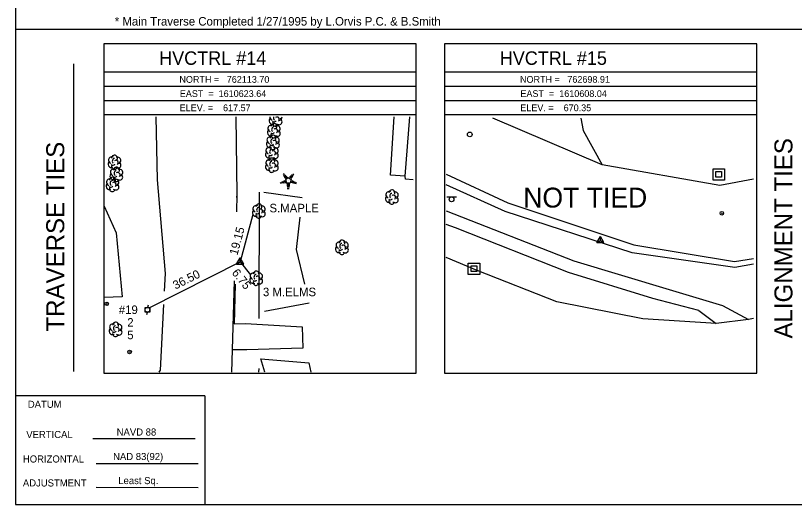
# Model space of a CAD drawing. Extents: x 1609637 to 1610277, y 761117 to 761537.
# Drawn here: x 1609637.2 to 1609911.6, y 761117.3 to 761289.4 of the extents above; entities that cross this region are included whole.
import ezdxf

# ---------------------------------------------------------------- set-up
doc = ezdxf.new("R2010")
doc.units = 0
for name, color, linetype in [('CPSM', 7, 'Continuous'), ('Default', 7, 'Continuous'), ('DS', 7, 'Continuous'), ('L_C', 7, 'Continuous'), ('LABL', 7, 'Continuous'), ('LAWA', 7, 'Continuous'), ('LBC', 7, 'Continuous'), ('LBF', 7, 'Continuous'), ('LFNC', 7, 'Continuous'), ('LSH', 7, 'Continuous'), ('LTC', 7, 'Continuous'), ('LTD', 7, 'Continuous'), ('NBL2', 7, 'Continuous'), ('PET', 7, 'Continuous'), ('PEU', 7, 'Continuous'), ('RDF', 7, 'Continuous'), ('RGR', 7, 'Continuous'), ('RSW', 7, 'Continuous'), ('SSGN', 7, 'Continuous'), ('U_C', 7, 'Continuous'), ('UP', 7, 'Continuous'), ('UPGW', 7, 'Continuous'), ('USMH', 7, 'Continuous'), ('UWV', 7, 'Continuous')]:
    doc.layers.add(name, color=color, linetype=linetype)

msp = doc.modelspace()

# ---------------------------------------------------------------- linework, layer by layer
at = {"layer": 'CPSM'}
for p, q in [((1609842.03, 761209.5), (1609843.28, 761211.67)), ((1609844.53, 761209.5), (1609843.28, 761211.67)), ((1609843.28, 761210.22), (1609843.28, 761211.67)), ((1609842.03, 761209.5), (1609843.28, 761210.22)), ((1609842.03, 761209.5), (1609844.53, 761209.5)), ((1609843.28, 761210.22), (1609843.28, 761210.22)), ((1609843.28, 761210.22), (1609844.53, 761209.5)), ((1609715.11, 761201.94), (1609716.36, 761204.11)), ((1609715.11, 761201.94), (1609716.36, 761202.66)), ((1609717.61, 761201.94), (1609716.36, 761204.11)), ((1609716.36, 761202.66), (1609716.36, 761204.11)), ((1609716.36, 761202.66), (1609716.36, 761202.66)), ((1609716.36, 761202.66), (1609717.61, 761201.94)), ((1609715.11, 761201.94), (1609717.61, 761201.94))]:
    msp.add_line(p, q, dxfattribs=at)
at = {"layer": 'Default'}
for p, q in [((1609720.83, 761219.38), (1609716.36, 761202.66)), ((1609684.52, 761186.67), (1609716.36, 761202.66)), ((1609716.36, 761202.66), (1609719.99, 761198.15))]:
    msp.add_line(p, q, dxfattribs=at)
at = {"layer": 'DS'}
for p, q in [((1609882.99, 761235.49), (1609886.99, 761235.49)), ((1609882.99, 761231.49), (1609882.99, 761235.49)), ((1609886.99, 761235.49), (1609886.99, 761231.49)), ((1609883.99, 761232.49), (1609883.99, 761234.49)), ((1609883.99, 761234.49), (1609885.99, 761234.49)), ((1609885.99, 761232.49), (1609883.99, 761232.49)), ((1609884.99, 761233.49), (1609884.99, 761233.49)), ((1609884.99, 761233.49), (1609884.99, 761233.49)), ((1609885.99, 761234.49), (1609885.99, 761232.49)), ((1609886.99, 761231.49), (1609882.99, 761231.49)), ((1609796.74, 761202.29), (1609800.74, 761202.29)), ((1609796.74, 761198.29), (1609796.74, 761202.29)), ((1609800.74, 761202.29), (1609800.74, 761198.29)), ((1609797.74, 761199.29), (1609797.74, 761201.29)), ((1609797.74, 761201.29), (1609799.74, 761201.29)), ((1609798.74, 761200.29), (1609798.74, 761200.29)), ((1609798.74, 761200.29), (1609798.74, 761200.29)), ((1609799.74, 761201.29), (1609799.74, 761199.29)), ((1609800.74, 761198.29), (1609796.74, 761198.29)), ((1609799.74, 761199.29), (1609797.74, 761199.29))]:
    msp.add_line(p, q, dxfattribs=at)
at = {"layer": 'LABL'}
msp.add_lwpolyline([(1609668.5, 761222.29), (1609672.69, 761212.96), (1609674.75, 761190.41), (1609668.5, 761190.13)], dxfattribs=at)
at = {"layer": 'LAWA'}
for points in [[(1609724.66, 761227.21), (1609738.2, 761225.35)], [(1609737.43, 761218.44), (1609736.14, 761207.04), (1609739.05, 761194.79)], [(1609740.64, 761188.11), (1609724.98, 761185.21)], [(1609725, 761163.83), (1609723.63, 761168.5), (1609740.5, 761167.1), (1609741.22, 761163.83)]]:
    msp.add_lwpolyline(points, dxfattribs=at)
at = {"layer": 'LBC'}
msp.add_lwpolyline([(1609777.33, 761231.64), (1609774.55, 761231.86), (1609774.53, 761232.88), (1609776.18, 761253.73)], dxfattribs=at)
at = {"layer": 'LBF'}
msp.add_lwpolyline([(1609774.53, 761232.88), (1609769.27, 761233.25), (1609770.64, 761253.73)], dxfattribs=at)
at = {"layer": 'LFNC'}
for points in [[(1609723.05, 761182.72), (1609723.2, 761227.22)], [(1609722.96, 761163.83), (1609723.03, 761165.19)]]:
    msp.add_lwpolyline(points, dxfattribs=at)
at = {"layer": 'LSH'}
for p, q in [((1609728.83, 761253.05), (1609728.83, 761253.05)), ((1609728.83, 761253.05), (1609728.83, 761253.05)), ((1609728.21, 761248.95), (1609728.21, 761248.95)), ((1609728.21, 761248.95), (1609728.21, 761248.95)), ((1609727.88, 761244.83), (1609727.88, 761244.83)), ((1609727.88, 761244.83), (1609727.88, 761244.83)), ((1609727.5, 761241.14), (1609727.5, 761241.14)), ((1609727.5, 761241.14), (1609727.5, 761241.14)), ((1609727.49, 761236.79), (1609727.49, 761236.79)), ((1609727.49, 761236.79), (1609727.49, 761236.79))]:
    msp.add_line(p, q, dxfattribs=at)
for centre in [(1609728.26, 761250.38), (1609727.93, 761246.27), (1609727.55, 761242.58), (1609727.53, 761238.22)]:
    msp.add_arc(centre, 1.05, 335.5272, 180.9563, dxfattribs=at)
for centre, major_axis, ratio, start_param, end_param in [((1609727.74, 761252.34), (0.58, -1.04), 0.959034, 3.141593, 6.283185), ((1609728.04, 761253.72), (1.21, -0.51), 0.895232, 3.576686, 4.712389), ((1609728.83, 761251.55), (0.26, 1.06), 0.942809, 1.570796, 4.712389), ((1609728.37, 761252.3), (-0.625, -0.083), 0.423636, 0, 3.141593), ((1609728.62, 761253.51), (-0.208, -0.792), 0.645439, 4.608624, 6.283185), ((1609729.33, 761252.89), (-0.5, 0.667), 0.989748, 3.141593, 6.283185), ((1609729.83, 761252.22), (-1.09, 0.79), 0.841452, 1.570796, 4.712389), ((1609729.87, 761253.64), (-1.14, -0.48), 0.949671, 1.570796, 2.79864), ((1609727.13, 761248.24), (0.58, -1.04), 0.959034, 3.141593, 6.283185), ((1609727.42, 761249.62), (1.21, -0.51), 0.895232, 1.570796, 4.712389), ((1609728, 761249.41), (-0.208, -0.792), 0.645439, 3.141593, 6.283185), ((1609728.71, 761248.78), (-0.5, 0.667), 0.989748, 3.141593, 6.283185), ((1609729.21, 761248.12), (-1.09, 0.79), 0.841452, 1.570796, 4.712389), ((1609729.25, 761249.53), (-1.14, -0.48), 0.949671, 1.570796, 4.712389), ((1609727.09, 761245.5), (1.21, -0.51), 0.895232, 1.570796, 4.712389), ((1609727.68, 761245.29), (-0.208, -0.792), 0.645439, 3.141593, 6.283185), ((1609728.21, 761247.45), (0.26, 1.06), 0.942809, 1.570796, 4.712389), ((1609727.75, 761248.2), (-0.625, -0.083), 0.423636, 0, 3.141593), ((1609728.93, 761245.42), (-1.14, -0.48), 0.949671, 1.570796, 4.712389), ((1609726.8, 761244.12), (0.58, -1.04), 0.959034, 3.141593, 6.283185), ((1609727.88, 761243.33), (0.26, 1.06), 0.942809, 1.570796, 4.712389), ((1609727.43, 761244.08), (-0.625, -0.083), 0.423636, 0, 3.141593), ((1609728.38, 761244.67), (-0.5, 0.667), 0.989748, 3.141593, 6.283185), ((1609728.88, 761244), (-1.09, 0.79), 0.841452, 1.570796, 4.712389), ((1609726.42, 761240.43), (0.58, -1.04), 0.959034, 3.141593, 6.283185), ((1609726.71, 761241.81), (1.21, -0.51), 0.895232, 1.570796, 4.712389), ((1609727.29, 761241.6), (-0.208, -0.792), 0.645439, 3.141593, 6.283185), ((1609728, 761240.98), (-0.5, 0.667), 0.989748, 3.141593, 6.283185), ((1609728.5, 761240.31), (-1.09, 0.79), 0.841452, 1.570796, 4.712389), ((1609728.54, 761241.73), (-1.14, -0.48), 0.949671, 1.570796, 4.712389), ((1609726.7, 761237.46), (1.21, -0.51), 0.895232, 1.570796, 4.712389), ((1609727.5, 761239.64), (0.26, 1.06), 0.942809, 1.570796, 4.712389), ((1609727.04, 761240.39), (-0.625, -0.083), 0.423636, 0, 3.141593), ((1609727.28, 761237.25), (-0.208, -0.792), 0.645439, 3.141593, 6.283185), ((1609728.53, 761237.37), (-1.14, -0.48), 0.949671, 1.570796, 4.712389), ((1609726.4, 761236.08), (0.58, -1.04), 0.959034, 3.141593, 6.283185), ((1609727.49, 761235.29), (0.26, 1.06), 0.942809, 1.570796, 4.712389), ((1609727.03, 761236.04), (-0.625, -0.083), 0.423636, 0, 3.141593), ((1609727.99, 761236.62), (-0.5, 0.667), 0.989748, 3.141593, 6.283185), ((1609728.49, 761235.96), (-1.09, 0.79), 0.841452, 1.570796, 4.712389)]:
    msp.add_ellipse(centre, major_axis=major_axis, ratio=ratio, start_param=start_param, end_param=end_param, dxfattribs=at)
at = {"layer": 'LTC'}
for p, q in [((1609731.46, 761233.51), (1609731.81, 761233.77)), ((1609731.67, 761233.05), (1609732.2, 761233.43)), ((1609731.88, 761232.58), (1609732.58, 761233.09)), ((1609732.09, 761232.12), (1609732.96, 761232.75)), ((1609732.31, 761231.66), (1609733.32, 761232.4)), ((1609733.32, 761232.4), (1609734.32, 761231.67)), ((1609733.74, 761232.71), (1609734.55, 761232.12)), ((1609734.11, 761233.06), (1609734.79, 761232.56)), ((1609734.48, 761233.41), (1609735.03, 761233.01)), ((1609734.86, 761233.75), (1609735.27, 761233.45)), ((1609730.49, 761230.79), (1609730.64, 761230.33)), ((1609730.95, 761231.01), (1609731.16, 761230.36)), ((1609731.4, 761231.23), (1609731.67, 761230.39)), ((1609731.86, 761231.44), (1609732.19, 761230.42)), ((1609732.31, 761231.66), (1609732.7, 761230.47)), ((1609733.93, 761230.47), (1609732.7, 761230.47)), ((1609733.89, 761229.97), (1609732.75, 761229.97)), ((1609734.32, 761231.67), (1609733.93, 761230.47)), ((1609734.76, 761231.4), (1609734.42, 761230.36)), ((1609735.2, 761231.15), (1609734.91, 761230.27)), ((1609735.65, 761230.9), (1609735.41, 761230.17)), ((1609736.09, 761230.65), (1609735.9, 761230.08)), ((1609733.81, 761229.47), (1609732.82, 761229.47)), ((1609733.72, 761228.97), (1609732.89, 761228.97)), ((1609733.64, 761228.47), (1609732.96, 761228.47))]:
    msp.add_line(p, q, dxfattribs=at)
at = {"layer": 'LTD'}
for p, q in [((1609672.05, 761237.81), (1609672.05, 761237.81)), ((1609672.05, 761237.81), (1609672.05, 761237.81)), ((1609672.72, 761233.55), (1609672.72, 761233.55)), ((1609672.72, 761233.55), (1609672.72, 761233.55)), ((1609671.33, 761230.05), (1609671.33, 761230.05)), ((1609671.33, 761230.05), (1609671.33, 761230.05)), ((1609769.79, 761225.58), (1609769.79, 761225.58)), ((1609769.79, 761225.58), (1609769.79, 761225.58)), ((1609722.92, 761220.65), (1609722.92, 761220.65)), ((1609722.92, 761220.65), (1609722.92, 761220.65)), ((1609752.2, 761207.89), (1609752.2, 761207.89)), ((1609752.2, 761207.89), (1609752.2, 761207.89)), ((1609721.99, 761196.98), (1609721.99, 761196.98)), ((1609721.99, 761196.98), (1609721.99, 761196.98)), ((1609672.45, 761178.96), (1609672.45, 761178.96)), ((1609672.45, 761178.96), (1609672.45, 761178.96))]:
    msp.add_line(p, q, dxfattribs=at)
for centre in [(1609672.09, 761239.24), (1609672.76, 761234.98), (1609671.38, 761231.49), (1609769.84, 761227.01), (1609722.96, 761222.09), (1609752.24, 761209.33), (1609722.04, 761198.41), (1609672.5, 761180.39)]:
    msp.add_arc(centre, 1.05, 335.5272, 180.9563, dxfattribs=at)
for centre, major_axis, ratio, start_param, end_param in [((1609670.96, 761237.1), (0.58, -1.04), 0.959034, 3.141593, 6.283185), ((1609671.26, 761238.48), (1.21, -0.51), 0.895232, 1.570796, 4.712389), ((1609671.84, 761238.27), (-0.208, -0.792), 0.645439, 3.141593, 6.283185), ((1609672.55, 761237.64), (-0.5, 0.667), 0.989748, 3.141593, 6.283185), ((1609673.05, 761236.98), (-1.09, 0.79), 0.841452, 1.570796, 4.712389), ((1609673.09, 761238.39), (-1.14, -0.48), 0.949671, 1.570796, 4.712389), ((1609671.93, 761234.22), (1.21, -0.51), 0.895232, 1.570796, 4.712389), ((1609672.05, 761236.31), (0.26, 1.06), 0.942809, 1.570796, 4.712389), ((1609671.59, 761237.06), (-0.625, -0.083), 0.423636, 0, 3.141593), ((1609673.76, 761234.13), (-1.14, -0.48), 0.949671, 1.570796, 4.712389), ((1609671.63, 761232.84), (0.58, -1.04), 0.959034, 3.141593, 6.283185), ((1609672.26, 761232.8), (-0.625, -0.083), 0.423636, 0, 3.141593), ((1609672.51, 761234.01), (-0.208, -0.792), 0.645439, 3.141593, 6.283185), ((1609673.22, 761233.38), (-0.5, 0.667), 0.989748, 3.141593, 6.283185), ((1609673.72, 761232.72), (-1.09, 0.79), 0.841452, 1.570796, 4.712389), ((1609670.25, 761229.35), (0.58, -1.04), 0.959034, 3.141593, 6.283185), ((1609670.54, 761230.72), (1.21, -0.51), 0.895232, 1.570796, 4.712389), ((1609671.12, 761230.51), (-0.208, -0.792), 0.645439, 3.141593, 6.283185), ((1609671.83, 761229.89), (-0.5, 0.667), 0.989748, 3.141593, 6.283185), ((1609672.72, 761232.05), (0.26, 1.06), 0.942809, 1.570796, 4.712389), ((1609672.33, 761229.22), (-1.09, 0.79), 0.841452, 1.570796, 4.712389), ((1609672.37, 761230.64), (-1.14, -0.48), 0.949671, 1.570796, 4.712389), ((1609671.33, 761228.55), (0.26, 1.06), 0.942809, 1.570796, 4.712389), ((1609670.87, 761229.3), (-0.625, -0.083), 0.423636, 0, 3.141593), ((1609769, 761226.25), (1.21, -0.51), 0.895232, 1.570796, 4.712389), ((1609769.58, 761226.04), (-0.208, -0.792), 0.645439, 3.141593, 6.283185), ((1609770.83, 761226.16), (-1.14, -0.48), 0.949671, 1.570796, 4.712389), ((1609768.71, 761224.87), (0.58, -1.04), 0.959034, 3.141593, 6.283185), ((1609769.79, 761224.08), (0.26, 1.06), 0.942809, 1.570796, 4.712389), ((1609769.33, 761224.83), (-0.625, -0.083), 0.423636, 0, 3.141593), ((1609770.29, 761225.41), (-0.5, 0.667), 0.989748, 3.141593, 6.283185), ((1609770.79, 761224.75), (-1.09, 0.79), 0.841452, 1.570796, 4.712389), ((1609722.12, 761221.32), (1.21, -0.51), 0.895232, 1.570796, 4.712389), ((1609722.71, 761221.11), (-0.208, -0.792), 0.645439, 3.141593, 6.283185), ((1609723.42, 761220.49), (-0.5, 0.667), 0.989748, 3.141593, 6.283185), ((1609723.96, 761221.24), (-1.14, -0.48), 0.949671, 1.570796, 4.712389), ((1609721.83, 761219.94), (0.58, -1.04), 0.959034, 3.141593, 6.283185), ((1609722.92, 761219.15), (0.26, 1.06), 0.942809, 1.570796, 4.712389), ((1609722.46, 761219.9), (-0.625, -0.083), 0.423636, 0, 3.141593), ((1609723.92, 761219.82), (-1.09, 0.79), 0.841452, 1.570796, 4.712389), ((1609751.11, 761207.18), (0.58, -1.04), 0.959034, 3.141593, 6.283185), ((1609751.41, 761208.56), (1.21, -0.51), 0.895232, 1.570796, 4.712389), ((1609751.99, 761208.35), (-0.208, -0.792), 0.645439, 3.141593, 6.283185), ((1609752.7, 761207.73), (-0.5, 0.667), 0.989748, 3.141593, 6.283185), ((1609753.2, 761207.06), (-1.09, 0.79), 0.841452, 1.570796, 4.712389), ((1609753.24, 761208.48), (-1.14, -0.48), 0.949671, 1.570796, 4.712389), ((1609752.2, 761206.39), (0.26, 1.06), 0.942809, 1.570796, 4.712389), ((1609751.74, 761207.14), (-0.625, -0.083), 0.423636, 0, 3.141593), ((1609720.91, 761196.27), (0.58, -1.04), 0.959034, 3.141593, 6.283185), ((1609721.2, 761197.64), (1.21, -0.51), 0.895232, 1.570796, 4.712389), ((1609721.78, 761197.43), (-0.208, -0.792), 0.645439, 3.141593, 6.283185), ((1609722.49, 761196.81), (-0.5, 0.667), 0.989748, 3.141593, 6.283185), ((1609722.99, 761196.14), (-1.09, 0.79), 0.841452, 1.570796, 4.712389), ((1609723.03, 761197.56), (-1.14, -0.48), 0.949671, 1.570796, 4.712389), ((1609721.99, 761195.48), (0.26, 1.06), 0.942809, 1.570796, 4.712389), ((1609721.53, 761196.23), (-0.625, -0.083), 0.423636, 0, 3.141593), ((1609671.66, 761179.63), (1.21, -0.51), 0.895232, 1.570796, 4.712389), ((1609672.24, 761179.42), (-0.208, -0.792), 0.645439, 3.141593, 6.283185), ((1609673.49, 761179.54), (-1.14, -0.48), 0.949671, 1.570796, 4.712389), ((1609671.37, 761178.25), (0.58, -1.04), 0.959034, 3.141593, 6.283185), ((1609672.45, 761177.46), (0.26, 1.06), 0.942809, 1.570796, 4.712389), ((1609671.99, 761178.21), (-0.625, -0.083), 0.423636, 0, 3.141593), ((1609672.95, 761178.79), (-0.5, 0.667), 0.989748, 3.141593, 6.283185), ((1609673.45, 761178.13), (-1.09, 0.79), 0.841452, 1.570796, 4.712389)]:
    msp.add_ellipse(centre, major_axis=major_axis, ratio=ratio, start_param=start_param, end_param=end_param, dxfattribs=at)
at = {"layer": 'NBL2'}
for p, q in [((1609637.23, 761284.62), (1610277.23, 761284.62)), ((1609657.7, 761164.07), (1609657.7, 761272.4)), ((1609778.33, 761269.45), (1609668.33, 761269.45)), ((1609898.33, 761269.45), (1609788.33, 761269.45)), ((1609778.33, 761264.45), (1609668.33, 761264.45)), ((1609898.33, 761264.45), (1609788.33, 761264.45)), ((1609778.33, 761259.45), (1609668.33, 761259.45)), ((1609898.33, 761259.45), (1609788.33, 761259.45)), ((1609778.33, 761254.45), (1609668.33, 761254.45)), ((1609898.33, 761254.45), (1609788.33, 761254.45)), ((1609703.9, 761155.54), (1609637.23, 761155.54)), ((1609703.9, 761155.54), (1609703.9, 761117.29)), ((1609703.9, 761155.54), (1609703.9, 761117.29)), ((1609664.47, 761140.52), (1609700.47, 761140.48)), ((1609665.58, 761131.74), (1609701.58, 761131.74)), ((1609665.58, 761123.31), (1609701.58, 761123.27))]:
    msp.add_line(p, q, dxfattribs=at)
for points in [[(1609637.23, 761117.29), (1610277.23, 761117.29), (1610277.23, 761537.29), (1609637.23, 761537.29)], [(1609668.33, 761163.45), (1609778.33, 761163.45), (1609778.33, 761279.45), (1609668.33, 761279.45)], [(1609788.33, 761163.45), (1609898.33, 761163.45), (1609898.33, 761279.45), (1609788.33, 761279.45)]]:
    msp.add_lwpolyline(points, close=True, dxfattribs=at)
at = {"layer": 'PET'}
for points in [[(1609689.72, 761192.37), (1609690.05, 761198.64), (1609687.22, 761231.56), (1609686.77, 761253.73)], [(1609714.8, 761253.73), (1609715.15, 761226.44), (1609715.12, 761225.36)], [(1609897.23, 761231.77), (1609885.4, 761229.63), (1609843.91, 761236.81), (1609805.32, 761253.25)], [(1609836.38, 761253.25), (1609837.16, 761248.92)], [(1609837.16, 761248.92), (1609843.91, 761236.81)], [(1609788.96, 761233.57), (1609810.68, 761223.48), (1609855.08, 761208.64), (1609890.52, 761202.8), (1609897.23, 761203.93)], [(1609714.23, 761196.05), (1609713.5, 761171.75), (1609713.36, 761163.83)], [(1609687.8, 761163.83), (1609688.25, 761164.59), (1609689.47, 761187.64)]]:
    msp.add_lwpolyline(points, dxfattribs=at)
at = {"layer": 'PEU'}
msp.add_lwpolyline([(1609897.23, 761182.7), (1609895.45, 761182.4), (1609884.05, 761180.99), (1609858.27, 761182.65), (1609827.93, 761188.59), (1609799.9, 761199.65), (1609788.96, 761204.22)], dxfattribs=at)
at = {"layer": 'RDF'}
for points in [[(1609715.15, 761226.44), (1609715.04, 761220.26)], [(1609714.56, 761194.81), (1609714.3, 761180.92), (1609718.25, 761181), (1609738.22, 761179.85), (1609738.39, 761172.3), (1609718.68, 761171.67), (1609713.5, 761171.75)]]:
    msp.add_lwpolyline(points, dxfattribs=at)
at = {"layer": 'RGR'}
msp.add_lwpolyline([(1609897.23, 761201.93), (1609890.65, 761200.73), (1609854.51, 761205.91), (1609809.73, 761220.43), (1609788.96, 761229.79)], dxfattribs=at)
at = {"layer": 'RSW'}
for points in [[(1609788.96, 761220.71), (1609833.89, 761203.1), (1609867.49, 761192.92), (1609886.3, 761187.29)], [(1609792.18, 761214.71), (1609788.96, 761215.83)], [(1609877.93, 761185.57), (1609861.77, 761189.78), (1609831.98, 761198.93), (1609792.18, 761214.71)], [(1609886.3, 761187.29), (1609895.45, 761182.4)], [(1609877.93, 761185.57), (1609884.05, 761180.99)]]:
    msp.add_lwpolyline(points, dxfattribs=at)
at = {"layer": 'SSGN'}
for p, q in [((1609789.18, 761225.56), (1609792.52, 761225.56)), ((1609790.83, 761224.72), (1609790.83, 761224.72))]:
    msp.add_line(p, q, dxfattribs=at)
msp.add_circle((1609790.83, 761224.72), 0.833, dxfattribs=at)
at = {"layer": 'UP'}
for p, q in [((1609682.85, 761185), (1609682.85, 761186.67)), ((1609682.85, 761186.67), (1609684.52, 761186.67)), ((1609683.94, 761187.5), (1609683.69, 761186.67)), ((1609683.69, 761185.83), (1609683.69, 761185.83)), ((1609684.52, 761186.67), (1609684.52, 761185)), ((1609684.52, 761185), (1609682.85, 761185)), ((1609683.44, 761184.17), (1609683.69, 761185))]:
    msp.add_line(p, q, dxfattribs=at)
msp.add_circle((1609683.69, 761185.83), 0.833, dxfattribs=at)
at = {"layer": 'UPGW'}
for centre, radius in [((1609669.35, 761187.9), 0.625), ((1609669.35, 761187.9), 0.0833), ((1609677.39, 761170.97), 0.625), ((1609677.39, 761170.97), 0.0833)]:
    msp.add_circle(centre, radius, dxfattribs=at)
at = {"layer": 'USMH'}
for p, q in [((1609797.25, 761247.58), (1609797.25, 761247.58)), ((1609798.09, 761247.58), (1609798.09, 761247.58))]:
    msp.add_line(p, q, dxfattribs=at)
msp.add_circle((1609797.25, 761247.58), 0.833, dxfattribs=at)
at = {"layer": 'UWV'}
for radius in [0.625, 0.0833]:
    msp.add_circle((1609886.07, 761219.82), radius, dxfattribs=at)

# ---------------------------------------------------------------- texts
at = {"layer": 'Default'}
for s, height, p in [('* Main Traverse Completed 1/27/1995 by L.Orvis P.C. & B.Smith', 3, (1609672.18, 761285.91)), ('NOT TIED', 7, (1609816.09, 761221.83))]:
    msp.add_text(s, height=height, dxfattribs=at).set_placement(p)
for s, rotation, p in [('19.15', 75.0093, (1609715.39, 761204.85)), ('36.50', 26.6788, (1609693.58, 761192.9)), ('6.75', 308.8188, (1609713.24, 761198.77))]:
    msp.add_text(s, height=3, rotation=rotation, dxfattribs=at).set_placement(p)
at = {"layer": 'L_C'}
for s, p in [('S.MAPLE', (1609726.68, 761220.14)), ('3 M.ELMS', (1609724.38, 761190.61))]:
    msp.add_text(s, height=3, dxfattribs=at).set_placement(p)
at = {"layer": 'LTC'}
msp.add_text('.', height=1.04, rotation=270, dxfattribs=at).set_placement((1609733.2, 761231.41))
at = {"layer": 'NBL2'}
for s, height, p in [('     HVCTRL #14    ', 4.75, (1609678.98, 761272.08)), ('     HVCTRL #15    ', 4.75, (1609798.98, 761272.08)), ('NORTH =   762113.70 ', 2.375, (1609694.95, 761265.76)), ('NORTH =   762698.91 ', 2.375, (1609814.95, 761265.76)), ('EAST  =  1610623.64 ', 2.375, (1609695.09, 761260.76)), ('EAST  =  1610608.04 ', 2.375, (1609815.09, 761260.76)), ('ELEV. =    617.57   ', 2.375, (1609695.05, 761255.76)), ('ELEV. =    670.35   ', 2.375, (1609815.05, 761255.76)), ('DATUM', 2.5, (1609641.55, 761151.3)), ('  NAVD 88 ', 2.5, (1609670.99, 761141.53)), ('HORIZONTAL', 2.5, (1609639.8, 761132.04)), ('NAD 83(92) ', 2.5, (1609671.59, 761132.91)), ('ADJUSTMENT', 2.5, (1609639.8, 761123.6)), (' Least Sq.', 2.5, (1609672.49, 761124.43))]:
    msp.add_text(s, height=height, dxfattribs=at).set_placement(p)
for s, height, rotation, p in [('TRAVERSE TIES', 6.3332, 90, (1609654.37, 761178.17)), ('ALIGNMENT TIES', 6.3332, 90, (1609910.93, 761175.69)), ('VERTICAL', 2.5, 0.1439, (1609641.01, 761140.63))]:
    msp.add_text(s, height=height, rotation=rotation, dxfattribs=at).set_placement(p)
at = {"layer": 'U_C'}
for s, p in [('#19', (1609673.6, 761184.34)), ('2', (1609676.58, 761179.9)), ('5', (1609676.58, 761175.46))]:
    msp.add_text(s, height=3, dxfattribs=at).set_placement(p)

doc.saveas('drawing.dxf')
